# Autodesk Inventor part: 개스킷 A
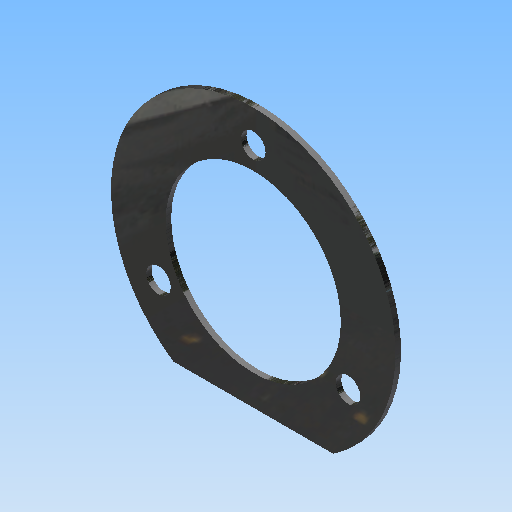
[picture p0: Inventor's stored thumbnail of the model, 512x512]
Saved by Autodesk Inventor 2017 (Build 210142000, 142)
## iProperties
Created: 2020-04
Part Number: 개스킷 A
Material: 고무
Document SubType Name: Modeling
Designer: mduedu
Density: 1 g/cm^3
Appearance: 고무 - 검은색 - 버전 1.1
Author: mduedu
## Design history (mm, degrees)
sketch "스케치1"
  geometry: C1 r 26 at (0, 0); 1 further point
  constraints: 1 centre point, 1 coincident
  dimensions: "d0" = 52 diameter of C1
extrude "돌출1" new body sketch "스케치1" distance "d1" = 1; taper "d2" = 0 deg
sketch "스케치2"
  geometry: L1 (-14.62, -21.5)-(14.62, -21.5); A1 r 26 centre (0, 0) between (-14.62, -21.5) and (14.62, -21.5) reference; 1 further point
  constraints: 2 end point, 2 point on circle, 1 horizontal
  dimensions: "d3" = 21.5 distance from line of L1 point (0, 0)
extrude "돌출2" cut sketch "스케치2" stored distance "d4" = 1; taper "d5" = 0 deg
sketch "스케치3" dims "d6" = 40
  geometry: 3 further points
  constraints: 2 vertical alignment, 1 coincident, 2 other
hole "구멍1" sketch "스케치3" at (0, 20) diameter "d7" = 4.5; stored, may be unused: countersink angle "d11" = 90 deg, drill point angle "d13" = 118 deg; dims "d8" = 6, "d9" = 4, "d10" = 2, "d12" = 8
sketch "스케치4"
  geometry: C1 r 16 at (0, 0); 1 further point
  constraints: 1 centre point, 1 coincident
  dimensions: "d17" = 32 diameter of C1
extrude "돌출3" cut sketch "스케치4" stored distance "d18" = 1; taper "d19" = 0 deg
node "솔리드1"
pattern_circular "원형 패턴1" dims angle "d15" = 360 deg
node "투영된 루프1"
